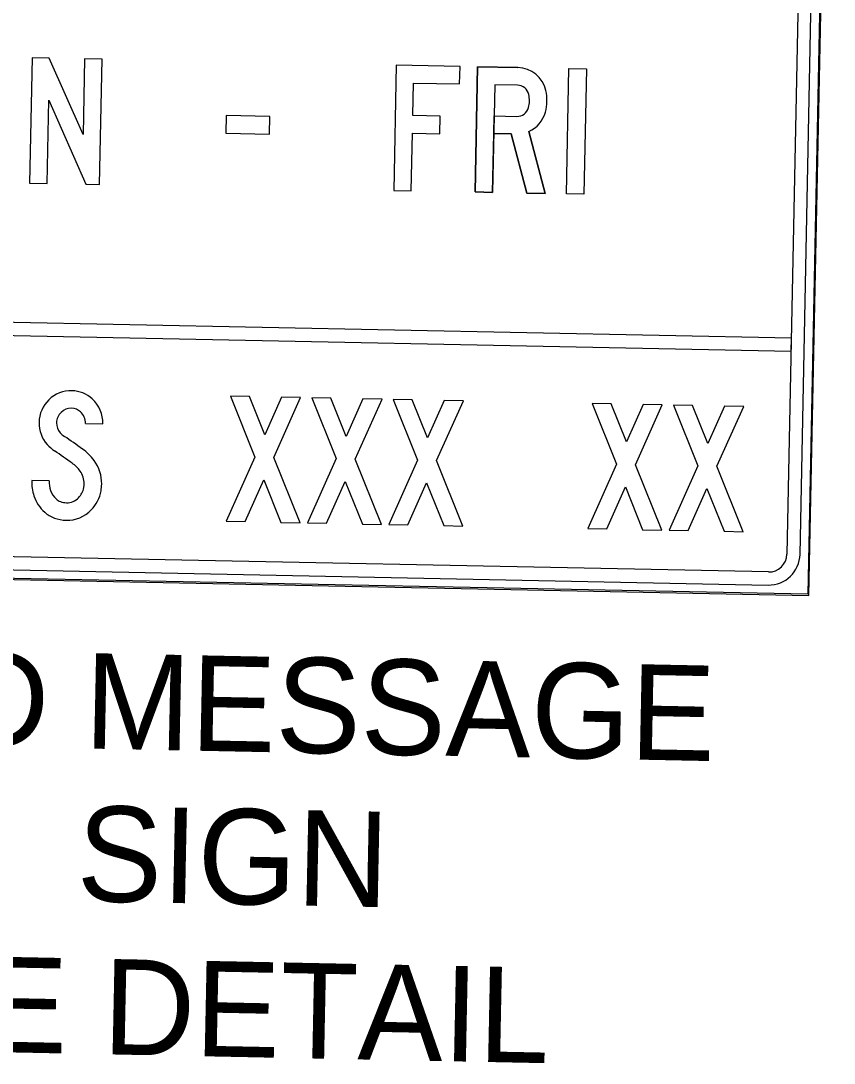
# Model space of a CAD drawing. Extents: x 331323 to 388339, y 121519 to 205315.
# Drawn here: x 368100 to 368612, y 133095 to 133750 of the extents above; entities that cross this region are included whole.
import ezdxf

# ---------------------------------------------------------------- set-up
doc = ezdxf.new("R2010")
doc.units = 0
doc.layers.add('P_MISC_TXT', color=7, linetype='Continuous')
doc.layers.add('P_SGN_Cell', color=7, linetype='Continuous')

msp = doc.modelspace()

# ---------------------------------------------------------------- linework, layer by layer
at = {"layer": 'P_MISC_TXT'}
for p, q in [((368611, 134175.28), (368595.19, 133389.5)), ((368596, 133388.66), (368611.84, 134176.08)), ((368596, 133388.66), (368611.84, 134176.08)), ((368596.97, 134150.54), (368582.16, 133414.78)), ((368590.36, 133414.62), (368605.17, 134150.37)), ((368412.79, 133720.67), (368387.5, 133721.18)), ((368412.57, 133709.65), (368412.57, 133709.65)), ((368412.18, 133689.97), (368412.18, 133689.97)), ((368412.18, 133689.97), (368412.18, 133689.97)), ((368584.9, 133550.51), (367826.18, 133565.77)), ((368584.9, 133550.51), (367826.18, 133565.77)), ((368584.9, 133550.51), (367826.18, 133565.77)), ((367826.01, 133557.57), (368584.73, 133542.31)), ((367826.01, 133557.57), (368584.73, 133542.31)), ((367826.01, 133557.57), (368584.73, 133542.31)), ((368584.73, 133542.31), (368584.9, 133550.51)), ((368584.73, 133542.31), (368584.9, 133550.51)), ((368584.73, 133542.31), (368584.9, 133550.51)), ((368570.45, 133403.53), (367834.78, 133418.33)), ((368595.19, 133389.5), (367808.59, 133405.32)), ((367834.61, 133410.13), (368570.29, 133395.33)), ((367808.58, 133404.5), (368596, 133388.66)), ((367808.58, 133404.5), (368596, 133388.66))]:
    msp.add_line(p, q, dxfattribs=at)
for points in [[(368141.07, 133647.38), (368149.73, 133647.21), (368151.32, 133725.94), (368140.3, 133726.16), (368139.34, 133678.58), (368118.12, 133726.6), (368107.23, 133726.82), (368105.65, 133648.1), (368116.67, 133647.87), (368117.72, 133700.23)], [(368141.07, 133647.38), (368149.73, 133647.21), (368151.32, 133725.94), (368140.3, 133726.16), (368139.34, 133678.58), (368118.12, 133726.6), (368107.23, 133726.82), (368105.65, 133648.1), (368116.67, 133647.87), (368117.72, 133700.23)], [(368141.07, 133647.38), (368149.73, 133647.21), (368151.32, 133725.94), (368140.3, 133726.16), (368139.34, 133678.58), (368118.12, 133726.6), (368107.23, 133726.82), (368105.65, 133648.1), (368116.67, 133647.87), (368117.72, 133700.23)], [(368346.49, 133679.48), (368363.74, 133679.13), (368363.96, 133690.15), (368346.71, 133690.5), (368347.12, 133710.97), (368376.25, 133710.38), (368376.47, 133721.4), (368336.32, 133722.21), (368334.74, 133643.49), (368345.76, 133643.26)], [(368346.49, 133679.48), (368363.74, 133679.13), (368363.96, 133690.15), (368346.71, 133690.5), (368347.12, 133710.97), (368376.25, 133710.38), (368376.47, 133721.4), (368336.32, 133722.21), (368334.74, 133643.49), (368345.76, 133643.26)], [(368346.49, 133679.48), (368363.74, 133679.13), (368363.96, 133690.15), (368346.71, 133690.5), (368347.12, 133710.97), (368376.25, 133710.38), (368376.47, 133721.4), (368336.32, 133722.21), (368334.74, 133643.49), (368345.76, 133643.26)], [(368444.97, 133720.03), (368455.99, 133719.8), (368454.4, 133641.08), (368443.38, 133641.3)], [(368444.97, 133720.03), (368455.99, 133719.8), (368454.4, 133641.08), (368443.38, 133641.3)], [(368444.97, 133720.03), (368455.99, 133719.8), (368454.4, 133641.08), (368443.38, 133641.3)], [(368229.14, 133679.48), (368256.7, 133678.92), (368256.92, 133689.94), (368229.36, 133690.5)], [(368229.14, 133679.48), (368256.7, 133678.92), (368256.92, 133689.94), (368229.36, 133690.5)], [(368229.14, 133679.48), (368256.7, 133678.92), (368256.92, 133689.94), (368229.36, 133690.5)], [(368253.13, 133461.56), (368263.85, 133434.72), (368275.82, 133434.48), (368259.4, 133475.59), (368276.22, 133513.23), (368264.26, 133513.47), (368253.7, 133489.85), (368244.11, 133513.88), (368232.14, 133514.12), (368247.43, 133475.83), (368229.37, 133435.42), (368241.34, 133435.18)], [(368253.13, 133461.56), (368263.85, 133434.72), (368275.82, 133434.48), (368259.4, 133475.59), (368276.22, 133513.23), (368264.26, 133513.47), (368253.7, 133489.85), (368244.11, 133513.88), (368232.14, 133514.12), (368247.43, 133475.83), (368229.37, 133435.42), (368241.34, 133435.18)], [(368253.13, 133461.56), (368263.85, 133434.72), (368275.82, 133434.48), (368259.4, 133475.59), (368276.22, 133513.23), (368264.26, 133513.47), (368253.7, 133489.85), (368244.11, 133513.88), (368232.14, 133514.12), (368247.43, 133475.83), (368229.37, 133435.42), (368241.34, 133435.18)], [(368304.31, 133460.53), (368315.03, 133433.69), (368326.99, 133433.45), (368310.57, 133474.56), (368327.4, 133512.2), (368315.43, 133512.44), (368304.87, 133488.82), (368295.28, 133512.85), (368283.31, 133513.09), (368298.61, 133474.8), (368280.55, 133434.39), (368292.51, 133434.15)], [(368304.31, 133460.53), (368315.03, 133433.69), (368326.99, 133433.45), (368310.57, 133474.56), (368327.4, 133512.2), (368315.43, 133512.44), (368304.87, 133488.82), (368295.28, 133512.85), (368283.31, 133513.09), (368298.61, 133474.8), (368280.55, 133434.39), (368292.51, 133434.15)], [(368304.31, 133460.53), (368315.03, 133433.69), (368326.99, 133433.45), (368310.57, 133474.56), (368327.4, 133512.2), (368315.43, 133512.44), (368304.87, 133488.82), (368295.28, 133512.85), (368283.31, 133513.09), (368298.61, 133474.8), (368280.55, 133434.39), (368292.51, 133434.15)], [(368355.48, 133459.5), (368366.2, 133432.66), (368378.17, 133432.42), (368361.75, 133473.53), (368378.57, 133511.17), (368366.6, 133511.41), (368356.05, 133487.79), (368346.45, 133511.82), (368334.48, 133512.06), (368349.78, 133473.77), (368331.72, 133433.36), (368343.68, 133433.12)], [(368355.48, 133459.5), (368366.2, 133432.66), (368378.17, 133432.42), (368361.75, 133473.53), (368378.57, 133511.17), (368366.6, 133511.41), (368356.05, 133487.79), (368346.45, 133511.82), (368334.48, 133512.06), (368349.78, 133473.77), (368331.72, 133433.36), (368343.68, 133433.12)], [(368355.48, 133459.5), (368366.2, 133432.66), (368378.17, 133432.42), (368361.75, 133473.53), (368378.57, 133511.17), (368366.6, 133511.41), (368356.05, 133487.79), (368346.45, 133511.82), (368334.48, 133512.06), (368349.78, 133473.77), (368331.72, 133433.36), (368343.68, 133433.12)], [(368480.65, 133456.98), (368491.37, 133430.14), (368503.34, 133429.9), (368486.92, 133471.01), (368503.74, 133508.65), (368491.78, 133508.89), (368481.22, 133485.28), (368471.62, 133509.3), (368459.66, 133509.54), (368474.95, 133471.25), (368456.89, 133430.84), (368468.86, 133430.6)], [(368480.65, 133456.98), (368491.37, 133430.14), (368503.34, 133429.9), (368486.92, 133471.01), (368503.74, 133508.65), (368491.78, 133508.89), (368481.22, 133485.28), (368471.62, 133509.3), (368459.66, 133509.54), (368474.95, 133471.25), (368456.89, 133430.84), (368468.86, 133430.6)], [(368480.65, 133456.98), (368491.37, 133430.14), (368503.34, 133429.9), (368486.92, 133471.01), (368503.74, 133508.65), (368491.78, 133508.89), (368481.22, 133485.28), (368471.62, 133509.3), (368459.66, 133509.54), (368474.95, 133471.25), (368456.89, 133430.84), (368468.86, 133430.6)], [(368531.82, 133455.95), (368542.54, 133429.11), (368554.51, 133428.87), (368538.09, 133469.98), (368554.92, 133507.62), (368542.95, 133507.86), (368532.39, 133484.25), (368522.8, 133508.27), (368510.83, 133508.51), (368526.12, 133470.22), (368508.06, 133429.81), (368520.03, 133429.57)], [(368531.82, 133455.95), (368542.54, 133429.11), (368554.51, 133428.87), (368538.09, 133469.98), (368554.92, 133507.62), (368542.95, 133507.86), (368532.39, 133484.25), (368522.8, 133508.27), (368510.83, 133508.51), (368526.12, 133470.22), (368508.06, 133429.81), (368520.03, 133429.57)], [(368531.82, 133455.95), (368542.54, 133429.11), (368554.51, 133428.87), (368538.09, 133469.98), (368554.92, 133507.62), (368542.95, 133507.86), (368532.39, 133484.25), (368522.8, 133508.27), (368510.83, 133508.51), (368526.12, 133470.22), (368508.06, 133429.81), (368520.03, 133429.57)]]:
    msp.add_lwpolyline(points, close=True, dxfattribs=at)
for points in [[(368387.5, 133721.18), (368385.91, 133642.46), (368396.93, 133642.24), (368397.68, 133679.24), (368408.75, 133679.01), (368418.54, 133641.8), (368430, 133641.57), (368419.76, 133680.5)], [(368412.57, 133709.65), (368398.3, 133709.94), (368396.93, 133642.24), (368385.91, 133642.46), (368387.5, 133721.18), (368412.79, 133720.67)], [(368412.57, 133709.65), (368398.3, 133709.94), (368396.93, 133642.24), (368385.91, 133642.46), (368387.5, 133721.18), (368412.79, 133720.67)], [(368412.57, 133709.65), (368398.3, 133709.94), (368397.9, 133690.26), (368412.18, 133689.97)], [(368419.76, 133680.5), (368430, 133641.57), (368418.54, 133641.8), (368408.75, 133679.01), (368397.68, 133679.24), (368397.9, 133690.26), (368412.18, 133689.97)], [(368419.76, 133680.5), (368430, 133641.57), (368418.54, 133641.8), (368408.75, 133679.01), (368397.68, 133679.24), (368397.9, 133690.26), (368412.18, 133689.97)], [(368140.83, 133496.99), (368151.85, 133496.77)], [(368140.83, 133496.99), (368151.85, 133496.77)], [(368140.83, 133496.99), (368151.85, 133496.77)], [(368118.05, 133460.83), (368107.03, 133461.05)], [(368118.05, 133460.83), (368107.03, 133461.05)], [(368118.05, 133460.83), (368107.03, 133461.05)]]:
    msp.add_lwpolyline(points, dxfattribs=at)
for radius in [19.69, 11.48]:
    msp.add_arc((368570.68, 133415.01), radius, 268.84724, 358.84724, dxfattribs=at)
for centre, major_axis, start_param, end_param in [((368412.42, 133702.17), (0.37, 18.5), 4.954755, 6.283185), ((368412.42, 133702.17), (0.37, 18.5), 4.954755, 6.283185), ((368412.42, 133702.17), (0.37, 18.5), 4.954755, 6.283185), ((368412.42, 133702.17), (0.15, 7.48), 4.954755, 6.283185), ((368412.42, 133702.17), (0.15, 7.48), 4.954755, 6.283185), ((368412.42, 133702.17), (0.15, 7.48), 4.954755, 6.283185), ((368402.82, 133700), (0.57, 28.34), 4.470023, 4.954755), ((368402.82, 133700), (0.57, 28.34), 4.470023, 4.954755), ((368402.82, 133700), (0.57, 28.34), 4.470023, 4.954755), ((368402.82, 133700), (0.35, 17.32), 4.470023, 4.954755), ((368402.82, 133700), (0.35, 17.32), 4.470023, 4.954755), ((368402.82, 133700), (0.35, 17.32), 4.470023, 4.954755), ((368412.33, 133697.45), (0.15, 7.48), 3.141593, 4.470023), ((368412.33, 133697.45), (0.15, 7.48), 3.141593, 4.470023), ((368412.33, 133697.45), (0.15, 7.48), 3.141593, 4.470023), ((368412.33, 133697.45), (0.37, 18.5), 3.574819, 4.470023), ((368412.33, 133697.45), (0.37, 18.5), 3.574819, 4.470023), ((368412.33, 133697.45), (0.37, 18.5), 3.574819, 4.470023), ((368131.92, 133497.22), (0.41, 20.28), 6.283184, 7.853982), ((368131.92, 133497.22), (0.41, 20.28), 6.283184, 7.853982), ((368131.92, 133497.22), (0.41, 20.28), 6.283184, 7.853982), ((368131.94, 133497.91), (0.39, 19.59), 5.561989, 6.283185), ((368131.94, 133497.91), (0.39, 19.59), 5.561989, 6.283185), ((368131.94, 133497.91), (0.39, 19.59), 5.561989, 6.283185), ((368131.27, 133497.18), (0.41, 20.58), 4.712389, 5.561989), ((368131.27, 133497.18), (0.41, 20.58), 4.712389, 5.561989), ((368131.27, 133497.18), (0.41, 20.58), 4.712389, 5.561989), ((368131.92, 133497.22), (0.19, 9.26), 6.283183, 7.853981), ((368131.92, 133497.22), (0.19, 9.26), 6.283183, 7.853981), ((368131.92, 133497.22), (0.19, 9.26), 6.283183, 7.853981), ((368131.94, 133497.91), (0.17, 8.57), 5.561989, 6.283185), ((368131.94, 133497.91), (0.17, 8.57), 5.561989, 6.283185), ((368131.94, 133497.91), (0.17, 8.57), 5.561989, 6.283185), ((368131.27, 133497.18), (0.19, 9.56), 4.712389, 5.561989), ((368131.27, 133497.18), (0.19, 9.56), 4.712389, 5.561989), ((368131.27, 133497.18), (0.19, 9.56), 4.712389, 5.561989), ((368131.96, 133497.22), (0.41, 20.32), 1.570796, 2.321595), ((368131.96, 133497.22), (0.41, 20.32), 1.570796, 2.321595), ((368131.96, 133497.22), (0.41, 20.32), 1.570796, 2.321595), ((368131.96, 133497.22), (0.19, 9.3), 1.570796, 2.321595), ((368131.96, 133497.22), (0.19, 9.3), 1.570796, 2.321595), ((368131.96, 133497.22), (0.19, 9.3), 1.570796, 2.321595), ((368135.37, 133500.28), (0.28, 13.88), 2.321595, 2.56746), ((368135.37, 133500.28), (0.28, 13.88), 2.321595, 2.56746), ((368135.37, 133500.28), (0.28, 13.88), 2.321595, 2.56746), ((368135.37, 133500.28), (0.5, 24.9), 2.321595, 2.56746), ((368135.37, 133500.28), (0.5, 24.9), 2.321595, 2.56746), ((368135.37, 133500.28), (0.5, 24.9), 2.321595, 2.56746), ((367868.13, 133104.78), (9.32, 463.35), 5.679143, 5.709053), ((367868.13, 133104.78), (9.32, 463.35), 5.679143, 5.709053), ((367868.13, 133104.78), (9.32, 463.35), 5.679143, 5.709053), ((367868.13, 133104.78), (9.1, 452.33), 5.679143, 5.709053), ((367868.13, 133104.78), (9.1, 452.33), 5.679143, 5.709053), ((367868.13, 133104.78), (9.1, 452.33), 5.679143, 5.709053), ((368119.15, 133453.33), (0.68, 33.9), 5.373599, 5.679143), ((368119.15, 133453.33), (0.68, 33.9), 5.373599, 5.679143), ((368119.15, 133453.33), (0.68, 33.9), 5.373599, 5.679143), ((368119.15, 133453.33), (0.46, 22.88), 5.373599, 5.679143), ((368119.15, 133453.33), (0.46, 22.88), 5.373599, 5.679143), ((368119.15, 133453.33), (0.46, 22.88), 5.373599, 5.679143), ((368127.1, 133459.27), (0.48, 23.98), 4.712389, 5.373599), ((368127.1, 133459.27), (0.48, 23.98), 4.712389, 5.373599), ((368127.1, 133459.27), (0.48, 23.98), 4.712389, 5.373599), ((368127.1, 133459.27), (0.26, 12.96), 4.712389, 5.373599), ((368127.1, 133459.27), (0.26, 12.96), 4.712389, 5.373599), ((368127.1, 133459.27), (0.26, 12.96), 4.712389, 5.373599), ((368136.06, 133460.47), (0.58, 29.04), 1.570808, 1.909921), ((368136.06, 133460.47), (0.58, 29.04), 1.570808, 1.909921), ((368136.06, 133460.47), (0.58, 29.04), 1.570808, 1.909921), ((368136.06, 133460.47), (0.36, 18.01), 1.570816, 1.909918), ((368136.06, 133460.47), (0.36, 18.01), 1.570816, 1.909918), ((368136.06, 133460.47), (0.36, 18.01), 1.570816, 1.909918), ((368124.87, 133459.31), (0.31, 15.19), 4.552917, 4.712389), ((368124.87, 133459.31), (0.31, 15.19), 4.552917, 4.712389), ((368124.87, 133459.31), (0.31, 15.19), 4.552917, 4.712389), ((368124.87, 133459.31), (0.53, 26.22), 4.552917, 4.712389), ((368124.87, 133459.31), (0.53, 26.22), 4.552917, 4.712389), ((368124.87, 133459.31), (0.53, 26.22), 4.552917, 4.712389), ((368131.05, 133458.82), (0.48, 23.76), 1.909925, 2.431476), ((368131.05, 133458.82), (0.48, 23.76), 1.909925, 2.431476), ((368131.05, 133458.82), (0.48, 23.76), 1.909925, 2.431476), ((368131.05, 133458.82), (0.26, 12.74), 1.909925, 2.431476), ((368131.05, 133458.82), (0.26, 12.74), 1.909925, 2.431476), ((368131.05, 133458.82), (0.26, 12.74), 1.909925, 2.431476), ((368127.66, 133458.81), (0.25, 12.36), 3.967076, 4.552917), ((368127.66, 133458.81), (0.25, 12.36), 3.967076, 4.552917), ((368127.66, 133458.81), (0.25, 12.36), 3.967076, 4.552917), ((368127.66, 133458.81), (0.47, 23.38), 3.967076, 4.552917), ((368127.66, 133458.81), (0.47, 23.38), 3.967076, 4.552917), ((368127.66, 133458.81), (0.47, 23.38), 3.967076, 4.552917), ((368127.75, 133455.13), (0.16, 7.79), 2.431476, 2.811358), ((368127.75, 133455.13), (0.16, 7.79), 2.431476, 2.811358), ((368127.75, 133455.13), (0.16, 7.79), 2.431476, 2.811358), ((368129.2, 133459.09), (0.24, 12.01), 2.811358, 3.141593), ((368129.2, 133459.09), (0.24, 12.01), 2.811358, 3.141593), ((368129.2, 133459.09), (0.24, 12.01), 2.811358, 3.141593), ((368129.16, 133457.36), (0.21, 10.28), 3.141593, 3.967076), ((368129.16, 133457.36), (0.21, 10.28), 3.141593, 3.967076), ((368129.16, 133457.36), (0.21, 10.28), 3.141593, 3.967076), ((368127.75, 133455.13), (0.38, 18.81), 2.431476, 2.811358), ((368127.75, 133455.13), (0.38, 18.81), 2.431476, 2.811358), ((368127.75, 133455.13), (0.38, 18.81), 2.431476, 2.811358), ((368129.2, 133459.09), (0.46, 23.03), 2.811358, 3.141593), ((368129.2, 133459.09), (0.46, 23.03), 2.811358, 3.141593), ((368129.2, 133459.09), (0.46, 23.03), 2.811358, 3.141593), ((368129.16, 133457.36), (0.43, 21.3), 3.141593, 3.967076), ((368129.16, 133457.36), (0.43, 21.3), 3.141593, 3.967076), ((368129.16, 133457.36), (0.43, 21.3), 3.141593, 3.967076)]:
    msp.add_ellipse(centre, major_axis=major_axis, ratio=0.999993, start_param=start_param, end_param=end_param, dxfattribs=at)

# ---------------------------------------------------------------- texts
at = {"layer": 'P_SGN_Cell'}
for s, p in [('FIXED MESSAGE', (367881.25, 133297.79)), ('SIGN', (368135.08, 133196.66)), ('SEE DETAIL', (367968.55, 133104))]:
    msp.add_text(s, height=60, rotation=358.84622, dxfattribs=at).set_placement(p)

doc.saveas('drawing.dxf')
